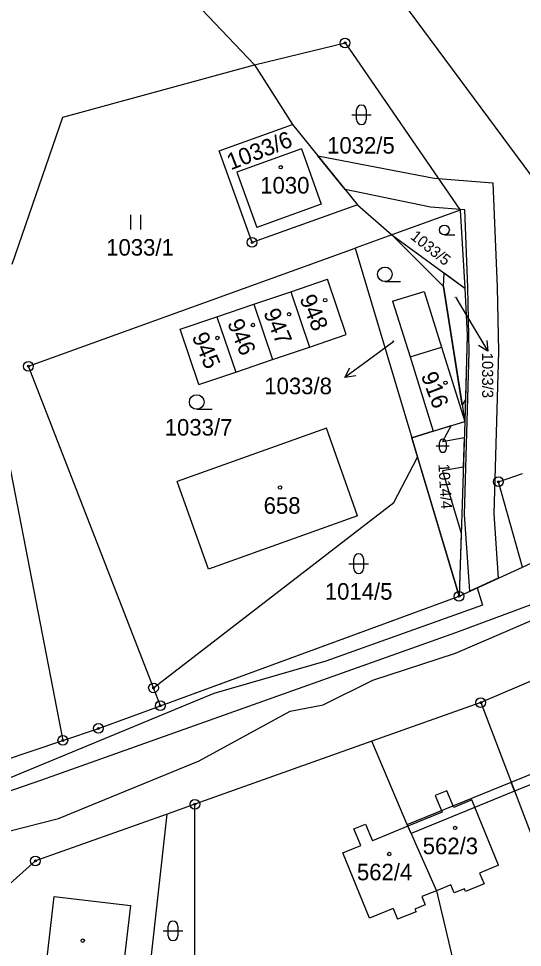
# Model space of a CAD drawing. Extents: x -439246 to -433691, y -1130252 to -1121148.
# Drawn here: x -438070.1 to -438018.3, y -1124216.2 to -1124120.8 of the extents above; entities that cross this region are included whole.
import ezdxf

# ---------------------------------------------------------------- set-up
doc = ezdxf.new("R2010")
doc.units = 0
for name, color, linetype in [('Vrstva 1', 7, 'Continuous'), ('Vrstva 16', 7, 'Continuous'), ('Vrstva 18', 7, 'Continuous'), ('Vrstva 19', 7, 'Continuous'), ('Vrstva 24', 7, 'Continuous'), ('Vrstva 25', 7, 'Continuous'), ('Vrstva 3', 7, 'Continuous'), ('Vrstva 30', 7, 'Continuous'), ('Vrstva 37', 7, 'Continuous'), ('Vrstva 4', 7, 'Continuous'), ('Vrstva 52', 7, 'Continuous')]:
    doc.layers.add(name, color=color, linetype=linetype)

msp = doc.modelspace()

# ---------------------------------------------------------------- linework, layer by layer
at = {"layer": 'Vrstva 1'}
for p, q in [((-438045.82, -1124125.58), (-438036.5, -1124123.32)), ((-438036.5, -1124123.32), (-438024.69, -1124140.51))]:
    msp.add_line(p, q, dxfattribs=at)
for points in [[(-438045.82, -1124125.58), (-438062.04, -1124108.49)], [(-438033.64, -1124114.99), (-438017.34, -1124137.01)], [(-438065.51, -1124130.95), (-438045.82, -1124125.58)], [(-438045.82, -1124125.58), (-438041.9, -1124131.7)], [(-438070.71, -1124146.05), (-438065.51, -1124130.95)], [(-438049.43, -1124134.4), (-438041.9, -1124131.7)], [(-438041.9, -1124131.7), (-438035.24, -1124139.94)], [(-438046.06, -1124143.81), (-438049.43, -1124134.4)], [(-438040.99, -1124134.2), (-438047.62, -1124136.58)], [(-438040.99, -1124134.2), (-438038.95, -1124139.89)], [(-438047.62, -1124136.58), (-438045.58, -1124142.28)], [(-438035.24, -1124139.94), (-438046.06, -1124143.81)], [(-438038.95, -1124139.89), (-438045.58, -1124142.28)], [(-438035.24, -1124139.94), (-438031.7, -1124143.04)], [(-438024.69, -1124140.51), (-438031.7, -1124143.04)], [(-438024.69, -1124140.51), (-438024.19, -1124148.5)], [(-438031.7, -1124143.04), (-438035.46, -1124144.4)], [(-438031.7, -1124143.04), (-438024.19, -1124148.5)], [(-438031.7, -1124143.04), (-438026.39, -1124148.35)], [(-438069.05, -1124156.54), (-438035.46, -1124144.4)], [(-438035.46, -1124144.4), (-438029.64, -1124163.9)], [(-438042.09, -1124148.88), (-438038.31, -1124147.6)], [(-438036.38, -1124153.28), (-438038.31, -1124147.6)], [(-438045.88, -1124150.17), (-438042.09, -1124148.88)], [(-438042.09, -1124148.88), (-438040.17, -1124154.57)], [(-438031.63, -1124149.86), (-438028.38, -1124148.84)], [(-438028.38, -1124148.84), (-438026.59, -1124154.57)], [(-438026.39, -1124148.35), (-438024.2, -1124162.2)], [(-438024.19, -1124148.5), (-438023.97, -1124153.33)], [(-438031.63, -1124149.86), (-438029.83, -1124155.58)], [(-438049.67, -1124151.45), (-438045.88, -1124150.17)], [(-438045.88, -1124150.17), (-438043.95, -1124155.85)], [(-438053.46, -1124152.74), (-438049.67, -1124151.45)], [(-438049.67, -1124151.45), (-438047.74, -1124157.14)], [(-438051.53, -1124158.42), (-438053.46, -1124152.74)], [(-438040.17, -1124154.57), (-438036.38, -1124153.28)], [(-438023.97, -1124153.33), (-438024.2, -1124162.2)], [(-438043.95, -1124155.85), (-438040.17, -1124154.57)], [(-438026.59, -1124154.57), (-438024.2, -1124162.2)], [(-438029.83, -1124155.58), (-438027.45, -1124163.22)], [(-438056.19, -1124189.58), (-438069.05, -1124156.54)], [(-438047.74, -1124157.14), (-438043.95, -1124155.85)], [(-438051.53, -1124158.42), (-438047.74, -1124157.14)], [(-438027.45, -1124163.22), (-438024.2, -1124162.2)], [(-438024.2, -1124162.2), (-438024.79, -1124180.17)], [(-438038.42, -1124162.9), (-438053.76, -1124168.39)], [(-438035.21, -1124171.89), (-438038.42, -1124162.9)], [(-438027.45, -1124163.22), (-438029.64, -1124163.9)], [(-438029.64, -1124163.9), (-438029.05, -1124165.86)], [(-438031.49, -1124170.53), (-438029.05, -1124165.86)], [(-438029.05, -1124165.86), (-438024.79, -1124180.17)], [(-438071.07, -1124166.37), (-438065.51, -1124194.98)], [(-438020.74, -1124168.4), (-438018.27, -1124167.55)], [(-438050.55, -1124177.38), (-438053.76, -1124168.39)], [(-438018.28, -1124177.17), (-438020.74, -1124168.4)], [(-438056.19, -1124189.58), (-438031.49, -1124170.53)], [(-438035.21, -1124171.89), (-438050.55, -1124177.38)], [(-438018.28, -1124177.17), (-438013.05, -1124174.75)], [(-438024.79, -1124180.17), (-438018.28, -1124177.17)], [(-438055.48, -1124191.41), (-438024.79, -1124180.17)], [(-438016.21, -1124180.62), (-438025.16, -1124183.92)], [(-438025.16, -1124183.92), (-438067.72, -1124199.06)], [(-438008.89, -1124185.25), (-438022.56, -1124191.1)], [(-438055.48, -1124191.41), (-438056.19, -1124189.58)], [(-438061.85, -1124193.74), (-438055.48, -1124191.41)], [(-438022.56, -1124191.1), (-438033.75, -1124195.07)], [(-438022.56, -1124191.1), (-438008.31, -1124228.46)], [(-438065.51, -1124194.98), (-438061.85, -1124193.74)], [(-438074.78, -1124198.12), (-438065.51, -1124194.98)], [(-438033.75, -1124195.07), (-438051.94, -1124201.54)], [(-438030.05, -1124203.79), (-438033.75, -1124195.07)], [(-438067.72, -1124199.06), (-438075.27, -1124201.65)], [(-438051.94, -1124201.54), (-438054.79, -1124202.55)], [(-438051.94, -1124227.09), (-438051.94, -1124201.54)], [(-438054.79, -1124202.55), (-438068.33, -1124207.36)], [(-438057.58, -1124227.84), (-438054.79, -1124202.55)], [(-438030.05, -1124203.79), (-438027.12, -1124210.42)], [(-438068.33, -1124207.36), (-438074.53, -1124212.85)], [(-438027.12, -1124210.42), (-438023.32, -1124226.48)]]:
    msp.add_lwpolyline(points, dxfattribs=at)
at = {"layer": 'Vrstva 16'}
for p, q in [((-438023.37, -1124152.42), (-438021.842, -1124155.002)), ((-438034.1, -1124155.92), (-438036.511, -1124157.706))]:
    msp.add_line(p, q, dxfattribs=at)
for points in [[(-438025.11, -1124149.48), (-438023.37, -1124152.42)], [(-438031.49, -1124153.99), (-438034.1, -1124155.92)], [(-438021.921, -1124153.886), (-438021.842, -1124155.002), (-438022.782, -1124154.396)], [(-438035.41, -1124157.512), (-438036.511, -1124157.706), (-438036.005, -1124156.709)]]:
    msp.add_lwpolyline(points, dxfattribs=at)
at = {"layer": 'Vrstva 24'}
for centre, radius in [((-438036.5, -1124123.32), 0.5), ((-438036.5, -1124123.32), 0.1), ((-438046.06, -1124143.81), 0.5), ((-438046.06, -1124143.81), 0.1), ((-438069.05, -1124156.54), 0.5), ((-438069.05, -1124156.54), 0.1), ((-438020.74, -1124168.4), 0.5), ((-438020.74, -1124168.4), 0.1), ((-438024.79, -1124180.17), 0.5), ((-438024.79, -1124180.17), 0.1), ((-438056.19, -1124189.58), 0.5), ((-438056.19, -1124189.58), 0.1), ((-438055.48, -1124191.41), 0.5), ((-438022.56, -1124191.1), 0.5), ((-438055.48, -1124191.41), 0.1), ((-438022.56, -1124191.1), 0.1), ((-438061.85, -1124193.74), 0.5), ((-438061.85, -1124193.74), 0.1), ((-438065.51, -1124194.98), 0.5), ((-438065.51, -1124194.98), 0.1), ((-438051.94, -1124201.54), 0.5), ((-438051.94, -1124201.54), 0.1), ((-438068.33, -1124207.36), 0.5), ((-438068.33, -1124207.36), 0.1)]:
    msp.add_circle(centre, radius, dxfattribs=at)
at = {"layer": 'Vrstva 25'}
for p, q in [((-438035.82, -1124130.7), (-438033.82, -1124130.7)), ((-438035.32, -1124131.2), (-438035.32, -1124130.2)), ((-438034.32, -1124130.2), (-438034.32, -1124131.2)), ((-438058.51, -1124142.47), (-438058.51, -1124140.97)), ((-438057.51, -1124142.47), (-438057.51, -1124140.97)), ((-438026.29, -1124143.03), (-438025.218, -1124143.03)), ((-438032.41, -1124147.84), (-438030.81, -1124147.84)), ((-438051.75, -1124160.96), (-438050.15, -1124160.96)), ((-438027.13, -1124164.71), (-438025.79, -1124164.71)), ((-438026.795, -1124165.045), (-438026.795, -1124164.375)), ((-438026.125, -1124164.375), (-438026.125, -1124165.045)), ((-438035.61, -1124177.32), (-438035.61, -1124176.32)), ((-438034.61, -1124176.32), (-438034.61, -1124177.32)), ((-438036.11, -1124176.82), (-438034.11, -1124176.82)), ((-438055.19, -1124214.55), (-438053.19, -1124214.55)), ((-438054.69, -1124215.05), (-438054.69, -1124214.05)), ((-438053.69, -1124214.05), (-438053.69, -1124215.05))]:
    msp.add_line(p, q, dxfattribs=at)
for centre, radius in [((-438043.11, -1124136.09), 0.175), ((-438026.29, -1124142.528), 0.503), ((-438032.41, -1124147.09), 0.75), ((-438038.55, -1124149.75), 0.175), ((-438042.26, -1124151.19), 0.175), ((-438045.97, -1124152.3), 0.175), ((-438049.62, -1124153.63), 0.175), ((-438026.18, -1124158.23), 0.175), ((-438051.75, -1124160.21), 0.75), ((-438043.19, -1124168.99), 0.175), ((-438025.2, -1124203.97), 0.175), ((-438031.96, -1124206.65), 0.175), ((-438063.46, -1124215.55), 0.175)]:
    msp.add_circle(centre, radius, dxfattribs=at)
for centre, radius, start, end in [((-438034.82, -1124130.2), 0.5, 0, 180), ((-438034.82, -1124131.2), 0.5, 180, 0), ((-438026.46, -1124164.375), 0.335, 0, 180), ((-438026.46, -1124165.045), 0.335, 180, 0), ((-438035.11, -1124176.32), 0.5, 0, 180), ((-438035.11, -1124177.32), 0.5, 180, 0), ((-438054.19, -1124214.05), 0.5, 0, 180), ((-438054.19, -1124215.05), 0.5, 180, 0)]:
    msp.add_arc(centre, radius, start, end, dxfattribs=at)
at = {"layer": 'Vrstva 3'}
for points in [[(-438040.99, -1124134.2), (-438047.62, -1124136.58)], [(-438040.99, -1124134.2), (-438038.95, -1124139.89)], [(-438047.62, -1124136.58), (-438045.58, -1124142.28)], [(-438038.95, -1124139.89), (-438045.58, -1124142.28)], [(-438042.09, -1124148.88), (-438038.31, -1124147.6)], [(-438036.38, -1124153.28), (-438038.31, -1124147.6)], [(-438045.88, -1124150.17), (-438042.09, -1124148.88)], [(-438042.09, -1124148.88), (-438040.17, -1124154.57)], [(-438042.09, -1124148.88), (-438040.17, -1124154.57)], [(-438049.67, -1124151.45), (-438045.88, -1124150.17)], [(-438045.88, -1124150.17), (-438043.95, -1124155.85)], [(-438045.88, -1124150.17), (-438043.95, -1124155.85)], [(-438053.46, -1124152.74), (-438049.67, -1124151.45)], [(-438049.67, -1124151.45), (-438047.74, -1124157.14)], [(-438049.67, -1124151.45), (-438047.74, -1124157.14)], [(-438051.53, -1124158.42), (-438053.46, -1124152.74)], [(-438040.17, -1124154.57), (-438036.38, -1124153.28)], [(-438043.95, -1124155.85), (-438040.17, -1124154.57)], [(-438029.83, -1124155.58), (-438026.59, -1124154.57)], [(-438026.59, -1124154.57), (-438024.2, -1124162.2)], [(-438029.83, -1124155.58), (-438027.45, -1124163.22)], [(-438047.74, -1124157.14), (-438043.95, -1124155.85)], [(-438051.53, -1124158.42), (-438047.74, -1124157.14)], [(-438027.45, -1124163.22), (-438024.2, -1124162.2)], [(-438038.42, -1124162.9), (-438053.76, -1124168.39)], [(-438035.21, -1124171.89), (-438038.42, -1124162.9)], [(-438050.55, -1124177.38), (-438053.76, -1124168.39)], [(-438035.21, -1124171.89), (-438050.55, -1124177.38)], [(-438026.03, -1124200.15), (-438027.24, -1124200.64)], [(-438025.33, -1124201.86), (-438026.03, -1124200.15)], [(-438027.24, -1124200.64), (-438026.53, -1124202.35)], [(-438023.48, -1124201.1), (-438025.33, -1124201.86)], [(-438020.73, -1124207.81), (-438023.48, -1124201.1)], [(-438026.53, -1124202.35), (-438030.05, -1124203.79)], [(-438035.59, -1124204.06), (-438034.39, -1124203.57)], [(-438034.89, -1124205.77), (-438035.59, -1124204.06)], [(-438034.39, -1124203.57), (-438033.69, -1124205.28)], [(-438030.05, -1124203.79), (-438033.69, -1124205.28)], [(-438030.05, -1124203.79), (-438027.12, -1124210.42)], [(-438030.05, -1124203.79), (-438027.12, -1124210.42)], [(-438036.74, -1124206.53), (-438034.89, -1124205.77)], [(-438033.99, -1124213.24), (-438036.74, -1124206.53)], [(-438020.73, -1124207.81), (-438022.68, -1124208.61)], [(-438022.68, -1124208.61), (-438022.22, -1124209.72)], [(-438025.64, -1124209.82), (-438027.12, -1124210.42)], [(-438025.3, -1124210.65), (-438025.64, -1124209.82)], [(-438022.22, -1124209.72), (-438024.12, -1124210.49)], [(-438067.96, -1124224.45), (-438066.39, -1124211.01)], [(-438066.39, -1124211.01), (-438058.56, -1124211.93)], [(-438027.12, -1124210.42), (-438028.6, -1124211.03)], [(-438024.23, -1124210.22), (-438025.3, -1124210.65)], [(-438024.12, -1124210.49), (-438024.23, -1124210.22)], [(-438058.56, -1124211.93), (-438059.8, -1124222.43)], [(-438028.26, -1124211.86), (-438029.32, -1124212.3)], [(-438028.6, -1124211.03), (-438028.26, -1124211.86)], [(-438031.56, -1124212.24), (-438033.99, -1124213.24)], [(-438031.56, -1124212.24), (-438031.11, -1124213.36)], [(-438029.21, -1124212.58), (-438031.11, -1124213.36)], [(-438029.32, -1124212.3), (-438029.21, -1124212.58)]]:
    msp.add_lwpolyline(points, dxfattribs=at)
at = {"layer": 'Vrstva 30'}
for p, q in [((-438024.2, -1124140.46), (-438027.74, -1124140.19)), ((-438023.87, -1124148.43), (-438024.2, -1124140.46)), ((-438023.74, -1124155.01), (-438023.87, -1124148.43)), ((-438024.24, -1124171.77), (-438023.74, -1124155.01)), ((-438023.67, -1124179.65), (-438024.24, -1124171.77)), ((-438020.76, -1124178.31), (-438023.67, -1124179.65))]:
    msp.add_line(p, q, dxfattribs=at)
for points in [[(-438027.74, -1124140.19), (-438036.49, -1124138.39), (-438039.31, -1124134.9), (-438027.36, -1124137.21), (-438021.31, -1124137.68), (-438020.87, -1124148.4), (-438020.74, -1124155.02), (-438021.23, -1124171.71), (-438020.76, -1124178.31)], [(-438026.33, -1124146.94), (-438024.19, -1124148.5), (-438023.97, -1124153.33), (-438024.14, -1124159.94), (-438024.46, -1124160.54), (-438026.39, -1124148.35), (-438026.33, -1124146.94)], [(-438026.48, -1124164.26), (-438024.25, -1124163.85), (-438024.35, -1124166.89), (-438026.49, -1124167.29), (-438024.58, -1124173.7), (-438024.79, -1124180.17), (-438029.64, -1124163.9), (-438025.6, -1124162.64), (-438026.48, -1124164.26)], [(-438055.48, -1124191.41), (-438037.54, -1124184.84), (-438024.79, -1124180.17), (-438022.91, -1124179.3), (-438022.38, -1124181.07)], [(-438022.38, -1124181.07), (-438038.49, -1124186.84), (-438049.98, -1124190.15), (-438082.11, -1124203.46), (-438100.75, -1124208.4), (-438114.97, -1124211.7), (-438135.97, -1124215.97), (-438152.44, -1124219.18), (-438172.51, -1124222.34), (-438177.48, -1124222.75), (-438171.25, -1124221.5), (-438165.02, -1124220.25), (-438154.18, -1124219.31), (-438150.01, -1124218.41), (-438131.51, -1124214.42), (-438127.95, -1124213.64), (-438114.32, -1124210.04), (-438095.78, -1124205.24), (-438074.78, -1124198.12), (-438065.51, -1124194.98), (-438061.85, -1124193.74), (-438055.48, -1124191.41)], [(-438013.93, -1124198.11), (-438019.08, -1124200.21), (-438019.44, -1124199.28), (-438013.85, -1124197), (-438005.19, -1124193.43), (-438004.78, -1124194.34), (-438013.01, -1124197.73), (-438003.93, -1124220.02), (-438003.47, -1124219.83), (-438002.72, -1124221.68), (-438004.57, -1124222.43), (-438005.32, -1124220.58), (-438004.86, -1124220.39), (-438013.93, -1124198.11)], [(-438019.08, -1124200.21), (-438029.72, -1124204.55), (-438030.12, -1124203.63), (-438019.44, -1124199.28), (-438019.08, -1124200.21)]]:
    msp.add_lwpolyline(points, dxfattribs=at)
at = {"layer": 'Vrstva 37'}
for centre in [(-438043.11, -1124136.09), (-438038.55, -1124149.75), (-438042.26, -1124151.19), (-438045.97, -1124152.3), (-438049.62, -1124153.63), (-438026.18, -1124158.23), (-438043.19, -1124168.99), (-438025.2, -1124203.97), (-438031.96, -1124206.65), (-438063.46, -1124215.55)]:
    msp.add_circle(centre, 0.175, dxfattribs=at)
at = {"layer": 'Vrstva 4'}
for points in [[(-438029.83, -1124155.58), (-438026.59, -1124154.57)], [(-438026.03, -1124200.15), (-438027.24, -1124200.64)], [(-438025.33, -1124201.86), (-438026.03, -1124200.15)], [(-438027.24, -1124200.64), (-438026.53, -1124202.35)], [(-438023.48, -1124201.1), (-438025.33, -1124201.86)], [(-438020.73, -1124207.81), (-438023.48, -1124201.1)], [(-438026.53, -1124202.35), (-438030.05, -1124203.79)], [(-438035.59, -1124204.06), (-438034.39, -1124203.57)], [(-438034.89, -1124205.77), (-438035.59, -1124204.06)], [(-438034.39, -1124203.57), (-438033.69, -1124205.28)], [(-438030.05, -1124203.79), (-438033.69, -1124205.28)], [(-438036.74, -1124206.53), (-438034.89, -1124205.77)], [(-438033.99, -1124213.24), (-438036.74, -1124206.53)], [(-438020.73, -1124207.81), (-438022.68, -1124208.61)], [(-438022.68, -1124208.61), (-438022.22, -1124209.72)], [(-438025.64, -1124209.82), (-438027.12, -1124210.42)], [(-438025.3, -1124210.65), (-438025.64, -1124209.82)], [(-438022.22, -1124209.72), (-438024.12, -1124210.49)], [(-438067.96, -1124224.45), (-438066.39, -1124211.01)], [(-438066.39, -1124211.01), (-438058.56, -1124211.93)], [(-438027.12, -1124210.42), (-438028.6, -1124211.03)], [(-438024.23, -1124210.22), (-438025.3, -1124210.65)], [(-438024.12, -1124210.49), (-438024.23, -1124210.22)], [(-438058.56, -1124211.93), (-438059.8, -1124222.43)], [(-438028.26, -1124211.86), (-438029.32, -1124212.3)], [(-438028.6, -1124211.03), (-438028.26, -1124211.86)], [(-438031.56, -1124212.24), (-438033.99, -1124213.24)], [(-438031.56, -1124212.24), (-438031.11, -1124213.36)], [(-438029.21, -1124212.58), (-438031.11, -1124213.36)], [(-438029.32, -1124212.3), (-438029.21, -1124212.58)]]:
    msp.add_lwpolyline(points, dxfattribs=at)
at = {"layer": 'Vrstva 52'}
msp.add_lwpolyline([(-438099.09, -1124216.4), (-438085.49, -1124210.45), (-438078.69, -1124208.33), (-438073.46, -1124205.56), (-438071.05, -1124204.29), (-438065.94, -1124203.01), (-438051.5, -1124197.07), (-438042.15, -1124191.97), (-438038.75, -1124191.33), (-438033.65, -1124188.78), (-438025.15, -1124186.02), (-438003.91, -1124176.88), (-437998.76, -1124173.66), (-437997.1, -1124172.63), (-437988.61, -1124170.29), (-437983.51, -1124166.68), (-437982.03, -1124165.98), (-437975.86, -1124163.07), (-437971.61, -1124159.88)], dxfattribs=at)

# ---------------------------------------------------------------- texts
at = {"layer": 'Vrstva 16'}
msp.add_text('1033/3', height=1.14, rotation=270.22383, dxfattribs=at).set_placement((-438022.43, -1124155.144))
msp.add_text('1033/8', height=1.7, dxfattribs=at).set_placement((-438044.806, -1124159.41))
at = {"layer": 'Vrstva 18'}
for s, height, rotation, p in [('1033/6', 1.7, 21.16512, (-438048.251, -1124136.412)), ('1033/5', 1.14, 321.30927, (-438029.87, -1124143.361)), ('1014/4', 1.14, 273.4065, (-438026.914, -1124166.59))]:
    msp.add_text(s, height=height, rotation=rotation, dxfattribs=at).set_placement(p)
for s, height, p in [('1032/5', 1.7, (-438038.348, -1124134.69)), ('1033/1', 1.7, (-438061.055, -1124145.17)), ('1033/3', 0.1, (-438025.325, -1124149.48)), ('1033/8', 0.1, (-438031.705, -1124153.99)), ('1033/7', 1.7, (-438055.038, -1124163.66)), ('1014/5', 1.7, (-438038.585, -1124180.52))]:
    msp.add_text(s, height=height, dxfattribs=at).set_placement(p)
at = {"layer": 'Vrstva 19'}
for s, p in [('1030', (-438045.222, -1124138.79)), ('658', (-438044.873, -1124171.69)), ('562/3', (-438028.524, -1124206.67)), ('562/4', (-438035.284, -1124209.35))]:
    msp.add_text(s, height=1.7, dxfattribs=at).set_placement(p)
for s, rotation, p in [('948', 292.75353, (-438041.217, -1124149.581)), ('947', 292.75353, (-438044.927, -1124151.011)), ('946', 292.75353, (-438048.643, -1124152.093)), ('945', 292.75353, (-438052.277, -1124153.471)), ('916', 290.8584, (-438028.73, -1124157.485))]:
    msp.add_text(s, height=1.7, rotation=rotation, dxfattribs=at).set_placement(p)

doc.saveas('drawing.dxf')
